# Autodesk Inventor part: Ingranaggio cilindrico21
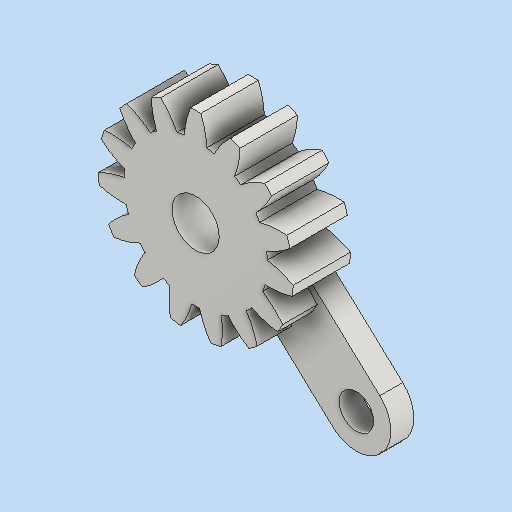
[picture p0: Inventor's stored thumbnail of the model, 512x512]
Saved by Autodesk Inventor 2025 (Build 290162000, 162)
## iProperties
CustomPartVersion: 1
Created: 2026-03
Part Number: Ingranaggio cilindrico21
Material: Steel
Document SubType Name: Modeling
Designer: R5800u
Categories: <?xml version="1.0" encoding="UTF-16"?> <MemberInstance><Categories><FamilyTemplate><FamilyTemplateParameter ValueType="xs:double" Id="1" ObjectReferenceKey="da
Density: 1 g/cm^3
Appearance: Steel
Author: R5800u
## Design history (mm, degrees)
sketch "Sketch1"
  geometry: C1 r 8.5 at (0, 0)
  constraints: 1 centre point
  dimensions: "d0" = 17 diameter of C1 (= da_da)
extrude "Extrusion1" new body sketch "Sketch1" distance "d1" = 5 (= da_b); taper "d2" = 0 deg
workplane "Work Plane2"
feature "Diametro primitivo" dims "d4" = 10, "d5" = 0
workplane "Work Plane8"
workplane "Work Plane9"
feature "Ingranaggio cilindrico" dims "da_b" = 5, "da_d" = 15, "da_aw" = 15, "da_da" = 17, "da_df" = 12.5, "da_dw" = 15, angle "da_beta" = 0 deg, "da_lefttooth" = 0, "da_righttooth" = 0
sketch "Schizzo3"
  geometry: A1 r 6.25 centre (0, 0) between (-6.173, 0.978) and (-6.241, 0.327) reference; 2 further points
  constraints: 1 coincident
hole "Foro1" sketch "Schizzo3" at (0, 0) diameter "d49" = 4.1; stored, may be unused: countersink angle "d53" = 90 deg, drill point angle "d55" = 118 deg; dims "d50" = 6, "d51" = 5.5, "d52" = 2.9, "d54" = 8
sketch "Schizzo4"
  geometry: L1 (0, 0)-(-14.318, -13.284); L2 (2.674, -1.612)-(-12.277, -15.483); L3 (-1.407, 2.787)-(-16.358, -11.085); C1 r 1.6 at (-14.318, -13.284) reference; C2 r 2.05 at (0, 0) reference; C3 r 3 at (-10.996, -10.202); C4 r 1.5 at (-10.996, -10.202); A1 r 7.077 centre (-8.037, 2.389) between (-7.129, -4.629) and (-4.857, -3.933) reference; 9 further points
  constraints: 6 end point, 2 centre point, 2 coincident, 2 parallel, 1 point on line, 1 tangent, 3 other
  dimensions: "d56" = 3 distance between parallel lines of L1 L2; "d57" = 3 distance between parallel lines of L1 L3; "d61" = 3 diameter of C4; "d62" = 15 distance of point (0, 0) C3.centre
  node "Riferimento1"
node "Piano di lavoro11"
extrude "Estrusione2" join sketch "Schizzo4" stored distance "d59" = 10; taper "d60" = 0 deg
body "Solid1"
sketch "Sketch2"
  geometry: C1 r 8.5 at (0, 0) reference; C2 r 7.5 at (0, 0)
  constraints: 1 centre point, 1 coincident
  dimensions: "d3" = 15 diameter of C2 (= da_d)
body "Srf1"
other parameters: "d16" = 15 (= da_aw), "d17" = 0, "d34" = 12 deg (computed from da_z), "d39" = 0, "d41" = 0, "d43" = 15 (= da_aw), "d46" = 15 (= da_aw), "d47" = 0, "d48" = 0
